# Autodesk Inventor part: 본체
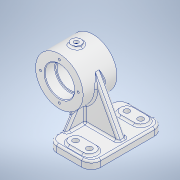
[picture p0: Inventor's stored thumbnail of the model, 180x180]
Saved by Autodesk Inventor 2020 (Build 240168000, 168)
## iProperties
Created: 2023-08
Part Number: 본체
Material: 알루미늄 6061
Document SubType Name: Modeling
Designer: oem
Density: 2.7 g/cm^3
Appearance: 알루미늄 - 평지
Mass: 777.553 g
Surface Area: 537.036 cm^2
Volume: 287.983 cm^3
Author: oem
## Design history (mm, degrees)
sketch "스케치1"
  geometry: C1 r 38 at (0, 0); 1 further point
  constraints: 1 centre point, 1 coincident
  dimensions: "d0" = 76 diameter of C1
extrude "돌출1" new body sketch "스케치1" stored distance "d1" = 54; taper "d2" = 0 deg
node "작업 평면1"
sketch "스케치2"
  geometry: L1 (-38, -27)-(38, -27) reference; L2 (-12, -58)-(-82, -58); L3 (-82, -58)-(-82, 58); L4 (-82, 58)-(-12, 58); L5 (-12, 58)-(-12, -58); L6 (-12, -58)-(-82, 58); L7 (-82, -58)-(-12, 58); 3 further points
  constraints: 12 end point, 3 midpoint, 2 parallel, 1 horizontal, 1 horizontal alignment, 1 perpendicular
  dimensions: "d4" = 116 distance of L2.end L3.end; "d5" = 70 distance of L2.start L2.end; "d6" = 82 distance from line of L3 point (0, 0)
extrude "돌출2" join sketch "스케치2" distance "d7" = 12; taper "d8" = 0 deg
fillet "모깎기1" dims "d9" = 15
sketch "스케치4"
  geometry: 1 further point
sketch "스케치5"
  geometry: L1 (82, -43)-(82, 43) reference; L2 (40, -41)-(62, -41); L3 (40, -51)-(62, -51); L4 (62, -31)-(40, -31); C1 r 4.5 at (40, -41); C2 r 4.5 at (62, -41); A1 r 10 centre (40, -41) between (40, -31) and (40, -51); A2 r 10 centre (62, -41) between (62, -51) and (62, -31); 2 further points
  constraints: 8 end point, 4 centre point, 4 point on circle, 4 tangent, 1 horizontal, 1 horizontal alignment, 1 midpoint, 1 parallel
  dimensions: "d10" = 9 diameter of C1; "d11" = 9 diameter of C2; "d12" = 22 distance of L2.end L2.start; "d13" = 20 distance from line of L1 L2.end; "d14" = 41 vertical distance of L2.end point (0, 0); "d15" = 20 diameter of A2
extrude "돌출3" join sketch "스케치5" distance "d16" = 3; taper "d17" = 0 deg
extrude "돌출4" cut sketch "스케치5" stored distance "d18" = 30; taper "d19" = 0 deg
node "작업 평면2"
sketch "스케치6"
  geometry: L1 (-38, -27)-(38, -27) reference; C1 r 8 at (0, 0); 1 further point
  constraints: 1 centre point, 1 coincident
  dimensions: "d21" = 16 diameter of C1
extrude "돌출5" join sketch "스케치6" stored distance "d22" = 30; taper "d23" = 0 deg
sketch "스케치7"
  geometry: L1 (38, 27)-(-38, 27) reference; L2 (0, 27)-(0, -27); L3 (-38, -27)-(38, -27) reference; L4 (23.5, 27)-(23.5, 10); L5 (23.5, 10)-(20.5, 10); L6 (20.5, 10)-(20.5, -10); L7 (20.5, -10)-(23.5, -10); L8 (23.5, -10)-(23.5, -27); 1 further point
  constraints: 12 end point, 4 point on line, 3 perpendicular, 2 midpoint, 1 collinear, 1 vertical
  dimensions: "d24" = 47 diameter of L4 L2; "d25" = 41 diameter of L6 L2; "d26" = 17 distance of L4.start L4.end
revolve "회전1" sketch "스케치7" stored, may be unused: angle "d27" = 90 deg
sketch "스케치8"
  geometry: C1 r 8 at (0, 0) reference; 2 further points
  constraints: 1 coincident
hole "구멍1" sketch "스케치8" at (0, 0) diameter "d28" = 5.1881; stored, may be unused: countersink angle "d32" = 90 deg, drill point angle "d34" = 0 deg; dims "d29" = 12, "d30" = 7, "d31" = 4, "d33" = 30
sketch "스케치9"
  geometry: C1 r 23.5 at (0, 0) reference; 1 further point
  constraints: 1 vertical alignment
  dimensions: "d35" = 30 distance of C1.centre point (0, 30)
hole "구멍2" sketch "스케치9" at (0, 30) diameter "d36" = 3.45873; stored, may be unused: countersink angle "d40" = 90 deg, drill point angle "d42" = 118 deg; dims "d37" = 8, "d38" = 7, "d39" = 4, "d41" = 10
fillet "모깎기2" dims "d46" = 1
chamfer "모따기1" distance "d47" = 1; stored, may be unused: second distance "d48" = 2, angle "d49" = 45 deg
fillet "모깎기3" dims "d50" = 3
node "작업 평면4"
sketch "스케치17"
  geometry: L1 (7, 12)-(26.815, 42.513); L2 (26.815, 42.513)-(59.185, 42.513); L3 (6.5, 0)-(6.5, 15) reference; L4 (59.185, 42.513)-(79, 12); L5 (86, 12)-(0, 12) reference; L6 (7, 12)-(79, 12); L7 (-15, 12)-(-15, 0) reference; L8 (101, 0)-(101, 12) reference; 1 further point
  constraints: 8 end point, 1 equal length, 1 parallel, 1 perpendicular, 1 point on line
  dimensions: "d78" = 22 distance from line of L7 L1.start; "d79" = 22 distance from line of L8 L4.end; "d80" = 33 deg angle of L7 L1; "d81" = 32.36973 distance of L1.end L2.end
extrude "돌출7" join sketch "스케치17" distance "d82" = 8; taper "d83" = 0 deg
sketch "스케치11"
  geometry: L1 (12, -58)-(27, -58) reference; L2 (67, -58)-(82, -58) reference; L3 (33.529, 17.882)-(74, -58); L4 (82, -58)-(82, -70) reference; L5 (12, -58)-(74, -58); 2 further points
  constraints: 4 end point, 1 collinear, 1 point on line, 3 other
  dimensions: "d51" = 8 distance from line of L4 L3.end
feature "리브1" sketch "스케치11" dims "d57" = 1, "d58" = 12, "d59" = 0, "d60" = 0, "d61" = 1, "d62" = 1
fillet "모깎기10" dims "d69" = 3
node "작업 평면3"
sketch "스케치15"
  geometry: L1 (70, -43)-(70, 43) reference; 3 further points
  constraints: 1 horizontal alignment, 1 midpoint, 1 other
  dimensions: "d71" = 19 distance from line of L1 point (51, 0)
fillet "모깎기11" dims "d84" = 3
fillet "모깎기12" dims "d85" = 3
fillet "모깎기13" dims "d86" = 3
fillet "모깎기14" dims "d87" = 3
fillet "모깎기15" dims "d88" = 3
fillet "모깎기16" dims "d89" = 3
feature "엠보싱1" dims "d0" = 76, "d90" = 0.5, "d91" = 0
node "솔리드1"
mirror "미러1"
pattern_circular "원형 패턴1" dims angle "d44" = 360 deg
mirror "미러2"
feature "A9D066F2-1C7D-4E18-AEED-F7BC21143FA4" dims "d28" = 5.1881, "d29" = 12, "d30" = 7, "d31" = 4, "d32" = 90 deg, "d33" = 30, "d34" = 0
other parameters: "d20" = 41, "d77" = -8
